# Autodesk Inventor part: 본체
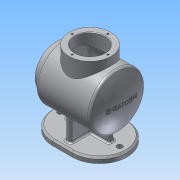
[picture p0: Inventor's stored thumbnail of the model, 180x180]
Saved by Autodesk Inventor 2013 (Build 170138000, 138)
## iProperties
Created: 2016-04
Part Number: 본체
Material: 알루미늄 6061
Document SubType Name: Modeling
Designer: Administrator
Density: 2.71 g/cm^3
Mass: 893.7 g
Surface Area: 1236.2 cm^2
Volume: 329.779 cm^3
Author: Administrator
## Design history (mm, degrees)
sketch "스케치1"
  geometry: 1 further point
sketch "스케치2"
  geometry: L1 (-17.5, 50)-(17.5, 50); L2 (-17.5, -50)-(17.5, -50); A1 r 50 centre (17.5, 0) between (17.5, -50) and (17.5, 50); A2 r 50 centre (-17.5, 0) between (-17.5, 50) and (-17.5, -50); 1 further point
  constraints: 4 end point, 4 point on circle, 2 centre point, 2 tangent, 1 horizontal, 1 parallel
  dimensions: "d7" = 0 vertical distance of A1.centre point (0, 0); "d8" = 100 diameter of A1; "d9" = 100 diameter of A2; "d10" = 0 vertical distance of point (0, 0) A2.centre; "d12" = 17.5 distance of A1.centre point (0, 0); "d13" = 17.5 distance of point (0, 0) A2.centre
extrude "돌출1" new body sketch "스케치2" distance "d14" = 10; taper "d15" = 0 deg
node "작업 평면1"
sketch "스케치3"
  geometry: L1 (-71.207, 79)-(106.129, 79); L2 (-44.5, 79)-(-44.5, 117); L3 (-44.5, 117)-(-32.5, 117); L4 (-32.5, 117)-(-32.5, 129); L5 (-32.5, 129)-(66.587, 129); L6 (-50, 0)-(0, 0) reference; L7 (85, 0)-(85, 10) reference; L8 (-50, 0)-(-50, 10) reference; L9 (64.645, 126)-(-29.5, 126); L10 (-29.5, 126)-(-29.5, 114); L11 (-29.5, 114)-(-41.5, 114); L12 (-41.5, 114)-(-41.5, 79); L13 (77.5, 79)-(74.5, 79); L14 (-41.5, 79)-(-44.5, 79); A1 r 120 centre (-42.5, 79) between (77.5, 79) and (66.587, 129); A2 r 117 centre (-42.5, 79) between (74.5, 79) and (64.645, 126); 1 further point
  constraints: 22 end point, 4 parallel, 4 point on circle, 3 perpendicular, 3 point on line, 2 centre point, 2 collinear, 1 horizontal, 4 other
  dimensions: "d16" = 79 distance from line of point (17.5, 0) L1; "d17" = 76 diameter of L3 L1; "d18" = 100 diameter of L5 L1; "d19" = 12 distance of L2.end L3.end; "d23" = 240 diameter of A1; "d25" = 2 distance from line of A1.centre L2; "d26" = 5.5 distance between parallel lines of L8 L2; "d27" = 3 radial gap between concentric circles of A1 A2
revolve "회전1" sketch "스케치3" stored, may be unused: angle "d28" = 90 deg
sketch "스케치4"
  geometry: C1 r 38 at (0, 0) reference; C2 r 35 at (0, 0); 1 further point
  constraints: 1 centre point, 1 coincident
  dimensions: "d29" = 70 diameter of C2
extrude "돌출2" cut sketch "스케치4" distance "d32" = 12; taper "d33" = 0 deg
sketch "스케치5"
  geometry: C1 r 35 at (0, 0) reference; C2 r 38 at (0, 0) reference; C3 r 27 at (0, 0); 1 further point
  constraints: 1 centre point, 1 coincident
  dimensions: "d34" = 54 diameter of C3
extrude "돌출3" join sketch "스케치5" distance "d36" = 12; taper "d37" = 0 deg
sketch "스케치6"
  geometry: L1 (50, 10)-(50, 0) reference; L2 (50, 0)-(-50, 0) reference; L3 (-50, 0)-(-50, 10) reference; L4 (-50, 10)-(50, 10) reference; L5 (40, 10)-(40, 14.339); L6 (40, 14.339)-(40, 49); L7 (-40, 10)-(-40, 49); C1 r 47 at (0, 79) reference; A1 r 50 centre (0, 79) between (40, 49) and (-40, 49) reference; 1 further point
  constraints: 6 end point, 3 perpendicular, 2 point on circle, 2 point on line
  dimensions: "d40" = 40 distance from line of A1.centre L7; "d41" = 40 distance from line of L6 point (0, 0)
extrude "돌출4" join sketch "스케치6" stored distance "d42" = 10; taper "d43" = 0 deg
node "작업 평면2"
sketch "스케치7"
  geometry: L1 (-50, 0)-(-50, 10) reference; L2 (-50, 10)-(12.5, 10) reference; L3 (12.5, 10)-(12.5, 29) reference; L4 (12.5, 29)-(-32.5, 29) reference; L5 (-32.5, 29)-(-32.5, 41) reference; L6 (-32.5, 41)-(-44.5, 41) reference; L7 (-44.5, 41)-(-44.5, 52) reference; L8 (-44.5, 52)-(-32.5, 52) reference; L9 (-32.5, 52)-(-32.5, 44) reference; L10 (-32.5, 44)-(-29.5, 44) reference; L11 (-29.5, 44)-(-29.5, 32) reference; L12 (-29.5, 32)-(64.645, 32) reference; L13 (64.645, 126)-(-29.5, 126) reference; L14 (-29.5, 126)-(-29.5, 114) reference; L15 (-29.5, 114)-(-32.5, 114) reference; L16 (-32.5, 114)-(-32.5, 106) reference; L17 (-32.5, 106)-(-44.5, 106) reference; L18 (-44.5, 106)-(-44.5, 117) reference; L19 (-44.5, 117)-(-32.5, 117) reference; L20 (-32.5, 117)-(-32.5, 129) reference; L21 (-32.5, 129)-(66.587, 129) reference; L22 (66.587, 29)-(22.5, 29) reference; L23 (22.5, 29)-(22.5, 10) reference; L24 (22.5, 10)-(85, 10) reference; L25 (85, 10)-(85, 0) reference; L26 (85, 0)-(-50, 0) reference; L27 (54.15, 29)-(57.5, 10); A1 r 117 centre (-42.5, 79) between (64.645, 32) and (64.645, 126) reference; A2 r 120 centre (-42.5, 79) between (66.587, 29) and (66.587, 129) reference; 1 further point
  constraints: 2 end point, 2 point on line
  dimensions: "d44" = 40 horizontal distance of L27.end point (17.5, 0); "d46" = 100 deg angle of L24 L27
feature "리브1" sketch "스케치7" dims "d48" = 1, "d49" = 10, "d50" = 0, "d51" = 0, "d52" = 1, "d53" = 1
fillet "모깎기1" dims "d54" = 3
fillet "모깎기2" dims "d55" = 3
chamfer "모따기1" distance "d56" = 3; stored, may be unused: second distance "d57" = 2, angle "d58" = 45 deg
fillet "모깎기3" dims "d59" = 5
node "작업 평면3"
sketch "스케치8"
  geometry: L1 (-50, -45)-(-50, 45) reference; L2 (-17.5, -50)-(17.5, -50) reference; C1 r 38 at (0, 0); 1 further point
  constraints: 1 centre point
  dimensions: "d62" = 50 distance from line of L1 C1.centre; "d64" = 50 distance from line of L2 C1.centre; "d65" = 76 diameter of C1
extrude "돌출5" join sketch "스케치8" stored distance "d66" = 10; taper "d67" = 0 deg
sketch "스케치9"
  geometry: C1 r 38 at (0, 0) reference; C2 r 27 at (0, 0); 1 further point
  constraints: 1 centre point, 1 coincident
  dimensions: "d68" = 54 diameter of C2
extrude "돌출6" cut sketch "스케치9" distance "d70" = 56.5; taper "d71" = 0 deg
chamfer "모따기2" distance "d72" = 1; stored, may be unused: second distance "d73" = 2, angle "d74" = 45 deg
chamfer "모따기3" distance "d75" = 1; stored, may be unused: second distance "d76" = 2, angle "d77" = 45 deg
sketch "스케치10"
  geometry: L1 (0, 0)-(32.5, 0); C1 r 28 at (0, 0) reference; 2 further points
  constraints: 2 end point, 1 coincident, 1 horizontal
  dimensions: "d78" = 32.5 distance of L1.start L1.end
hole "구멍1" sketch "스케치10" at (32.5, 0) diameter "d79" = 3.242; stored, may be unused: countersink angle "d83" = 90 deg, drill point angle "d85" = 118 deg; dims "d80" = 8, "d81" = 4, "d82" = 2, "d84" = 10
sketch "스케치11"
  geometry: L1 (0, 0)-(0, 32.5); C1 r 28 at (0, 0) reference; 2 further points
  constraints: 2 end point, 1 coincident, 1 vertical
  dimensions: "d89" = 32.5 distance of L1.start L1.end
hole "구멍2" sketch "스케치11" at (0, 32.5) diameter "d90" = 3.242; stored, may be unused: countersink angle "d94" = 90 deg, drill point angle "d96" = 118 deg; dims "d91" = 8, "d92" = 4, "d93" = 2, "d95" = 10
node "작업 평면4"
sketch "스케치12"
  geometry: L1 (-24.784, 15.761)-(24.784, 15.761); L2 (24.784, 15.761)-(24.784, -15.761); L3 (24.784, -15.761)-(-24.784, -15.761); L4 (-24.784, -15.761)-(-24.784, 15.761); L5 (-24.784, 0)-(24.784, 0); L6 (0, 15.761)-(0, -15.761); 2 further points
  constraints: 4 end point, 4 midpoint, 2 other
  dimensions: "d101" = 0 distance from line of point (0, 0) L6; "d102" = 0 distance from line of L5 point (0, 0)
feature "엠보싱1" sketch "스케치12" dims "d7" = 0, "d8" = 100, "d9" = 100, "d10" = 0, "d12" = 17.5, "d13" = 17.5, "d103" = 0.5, "d104" = 0
sketch "스케치13"
  geometry: C1 r 5 at (54, 0); C2 r 5 at (-54, 0); 1 further point
  constraints: 2 centre point
  dimensions: "d105" = 0 vertical distance of C2.centre point (0, 0); "d106" = 0 vertical distance of C1.centre point (0, 0); "d107" = 10 diameter of C1; "d108" = 10 diameter of C2; "d109" = 54 distance of C1.centre point (0, 0); "d110" = 54 distance of C2.centre point (0, 0)
extrude "돌출7" cut sketch "스케치13" distance "d111" = 56.5; taper "d112" = 0 deg
fillet "모깎기5" dims "d113" = 3
sketch "스케치14"
  geometry: 1 further point
sketch "스케치15"
  geometry: C1 r 27 at (0, 0) reference; C2 r 35 at (0, 0) reference; C3 r 35 at (0, 0); 1 further point
  constraints: 1 centre point, 1 coincident, 1 concentric
extrude "돌출8" join sketch "스케치15" distance "d114" = 3; taper "d115" = 0 deg
fillet "모깎기6" dims "d116" = 2
node "솔리드1"
mirror "대칭1"
pattern_circular "원형 패턴1" dims angle "d87" = 360 deg
pattern_circular "원형 패턴2" dims angle "d98" = 360 deg
node "절단 모서리 투영1"
node "절단 모서리 투영2"
other parameters: "d61" = -144, "d100" = -155
